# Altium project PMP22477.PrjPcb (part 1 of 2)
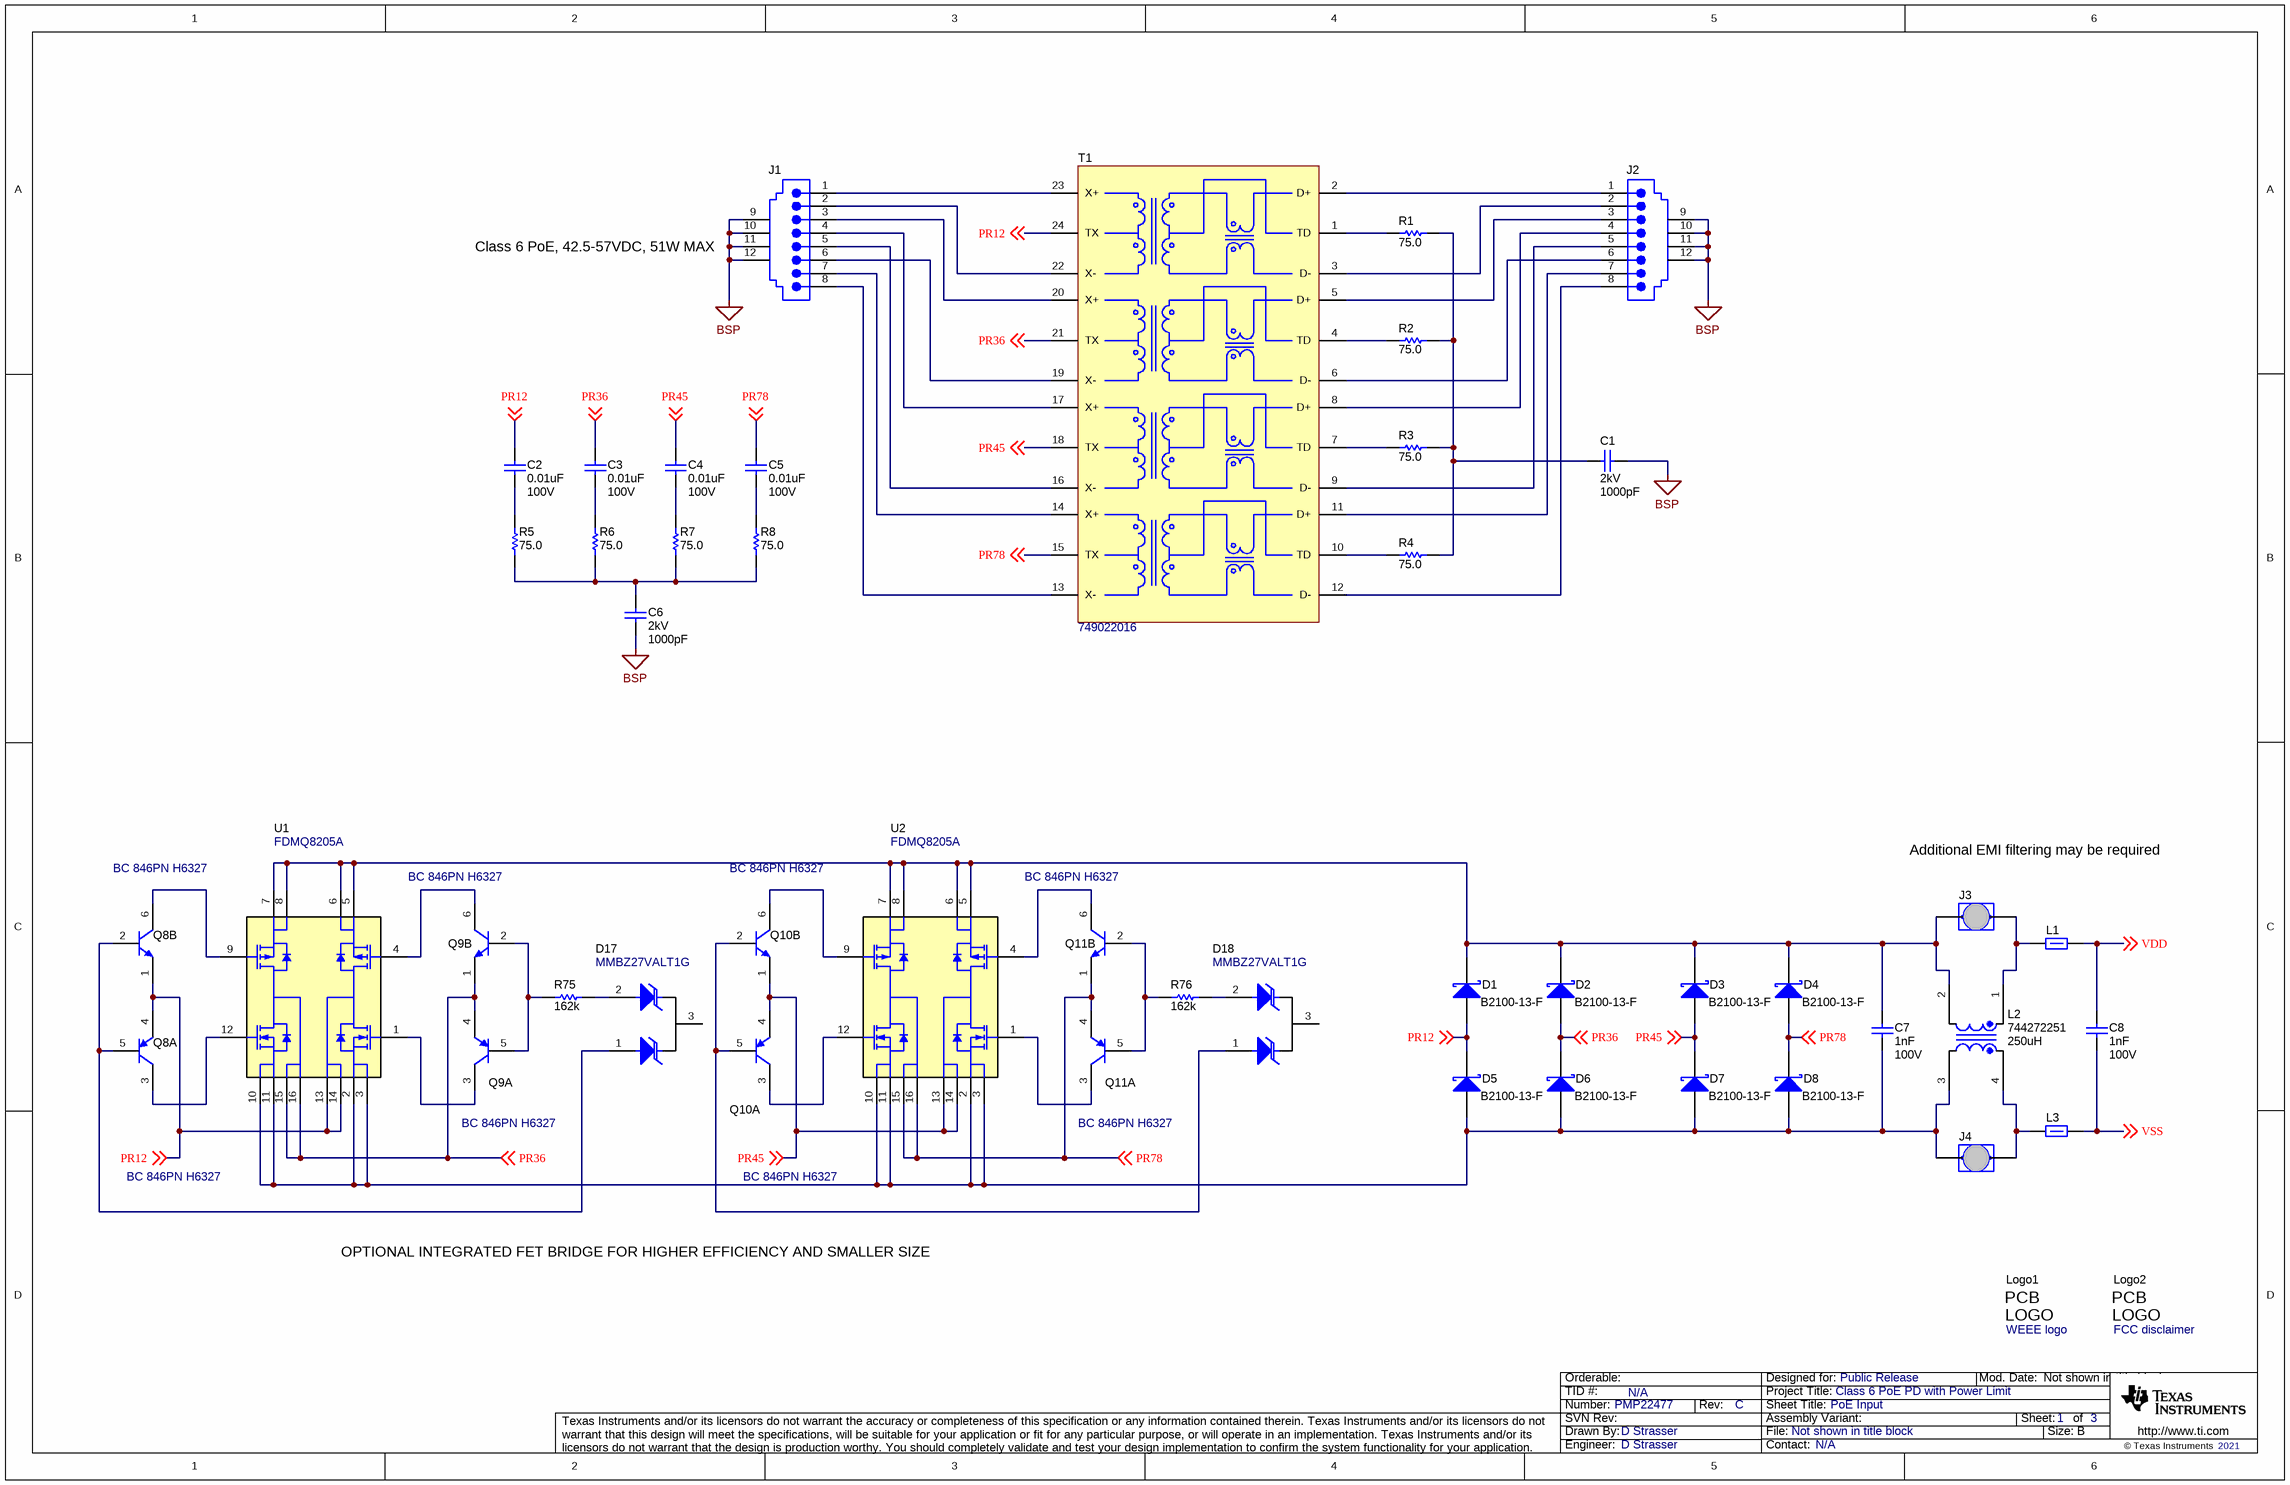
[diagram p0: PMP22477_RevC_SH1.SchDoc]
CopyrightYear: 2021; PCB_Layout: D Strasser; PCB_Rev: C; PRJ_Customer: Public Release; PRJ_Engineer: D Strasser; PRJ_Number: PMP22477; PRJ_Title: Class 6 PoE PD with Power Limit; SCH_Rev: C; TechSupport: N/A; TID: N/A
3 sheets, 191 parts. Net scope: global (net labels, ports and power ports of the same name join across sheets).
Board file: PMP22477_RevC.PcbDoc
Sheets:
  PMP22477_RevC_SH1.SchDoc
  PMP22477_RevC_SH2.SchDoc
  PMP22477_RevC_SH3.SchDoc

## Sheet PMP22477_RevC_SH1.SchDoc: PoE Input
size 431 x 279 mm; Date: Not shown in title block; ApprovedBy: Not shown in title block; CheckedBy: Not shown in title block; Author: Not shown in title block; CompanyName: Not shown in title block; DrawnBy: D Strasser; Engineer: Not shown in title block; Organization: Not shown in title block; Address1: Not shown in title block; Address2: Not shown in title block; Address3: Not shown in title block; Address4: Not shown in title block; DocumentNumber: 1; Revision: Use project parameter SCH_Rev; SheetNumber: 1; SheetTotal: 3; PageSetup: Record=PageOptions¦CenterHorizontal=True¦CenterVertical=True¦PrintScale=1.00¦XCorrection=1.00¦YCorrection=1.00¦PrintKind=0¦BorderSize=5000000¦LeftOffset=0¦BottomOffset=0¦Orientation=2¦PaperLength=1000¦PaperWidth=1000¦Scale=100¦PaperSource=15¦PrintQuality=600¦MediaType=1¦DitherType=10¦PaperKind=Letter¦PrintScaleMode=1

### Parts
C1  VDC_V: 2kV  ValueDisplayed: 1000pF  [1812]  (hidden comment: GR443QR73D102KW01L)
C2  ValueDisplayed: 0.01uF  Value2: 100V  [0603L]  (hidden comment: Capacitor)
C3  ValueDisplayed: 0.01uF  Value2: 100V  [0603L]  (hidden comment: Capacitor)
C4  ValueDisplayed: 0.01uF  Value2: 100V  [0603L]  (hidden comment: Capacitor)
C5  ValueDisplayed: 0.01uF  Value2: 100V  [0603L]  (hidden comment: Capacitor)
C6  VDC_V: 2kV  ValueDisplayed: 1000pF  [1812]  (hidden comment: GR443QR73D102KW01L)
C7  Cap_F: 1nF  VDC_V: 100V  [0603]  (hidden comment: C1608X7R2A102K080AA)
C8  Cap_F: 1nF  VDC_V: 100V  [0603]  (hidden comment: C1608X7R2A102K080AA)
D1  PartNumber: B2100-13-F  [SMB]  (hidden comment: CMP-0028397-2)
D2  PartNumber: B2100-13-F  [SMB]  (hidden comment: CMP-0028397-2)
D3  PartNumber: B2100-13-F  [SMB]  (hidden comment: CMP-0028397-2)
D4  PartNumber: B2100-13-F  [SMB]  (hidden comment: CMP-0028397-2)
D5  PartNumber: B2100-13-F  [SMB]  (hidden comment: CMP-0028397-2)
D6  PartNumber: B2100-13-F  [SMB]  (hidden comment: CMP-0028397-2)
D7  PartNumber: B2100-13-F  [SMB]  (hidden comment: CMP-0028397-2)
D8  PartNumber: B2100-13-F  [SMB]  (hidden comment: CMP-0028397-2)
D17  MMBZ27VALT1G  [SOT-23L]
D18  MMBZ27VALT1G  [SOT-23L]
J1  1-406541-1  [TEC_1-406541-1]  (value not drawn)
J2  1-406541-1  [TEC_1-406541-1]  (value not drawn)
J3  999-11-110-10-000000  [Mill-Max_999-11-110-10-000000]  (value not drawn)
J4  999-11-110-10-000000  [Mill-Max_999-11-110-10-000000]  (value not drawn)
L1  CMP-0003192-2  [0603]  (value not drawn)
L2  ValueDisplayed: 250uH  [WE-SL5]  (hidden comment: 744272251)
L3  CMP-0003192-2  [0603]  (value not drawn)
Logo1  WEEE logo  [WEEE_Minimum]  (no BOM)
Logo2  FCC disclaimer  [FCC_disclaimer]  (no BOM)
Q8  BC 846PN H6327  [SOT-363]  (parts A,B of 2)
Q9  BC 846PN H6327  [SOT-363]  (parts A,B of 2)
Q10  BC 846PN H6327  [SOT-363]  (parts A,B of 2)
Q11  BC 846PN H6327  [SOT-363]  (parts A,B of 2)
R1  ValueDisplayed: 75.0  [0603L]  (hidden comment: Resistor)
R2  ValueDisplayed: 75.0  [0603L]  (hidden comment: Resistor)
R3  ValueDisplayed: 75.0  [0603L]  (hidden comment: Resistor)
R4  ValueDisplayed: 75.0  [0603L]  (hidden comment: Resistor)
R5  ValueDisplayed: 75.0  [0603L]  (hidden comment: Resistor)
R6  ValueDisplayed: 75.0  [0603L]  (hidden comment: Resistor)
R7  ValueDisplayed: 75.0  [0603L]  (hidden comment: Resistor)
R8  ValueDisplayed: 75.0  [0603L]  (hidden comment: Resistor)
R75  ValueDisplayed: 162k  [0603L]  (hidden comment: CRCW0603162KFKEA)
R76  ValueDisplayed: 162k  [0603L]  (hidden comment: CRCW0603162KFKEA)
T1  749022016  [XFMR_749022016]
U1  FDMQ8205A  [MLP-4_5x5]
U2  FDMQ8205A  [MLP-4_5x5]

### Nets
BSP: C1.1 C6.2 J1.9 J1.10 J1.11 J1.12 J2.9 J2.10 J2.11 J2.12
PR12: C2.1 D1.2(A) D5.1(K) Q8.1(E) Q8.4(E) T1.24(TX) U1.13(INPUT1) U1.14(INPUT1) ; off-sheet PR12
PR36: C3.1 D2.2(A) D6.1(K) Q9.1(E) Q9.4(E) T1.21(TX) U1.15(INPUT2) U1.16(INPUT2) ; off-sheet PR36
PR45: C4.1 D3.2(A) D7.1(K) Q10.1(E) Q10.4(E) T1.18(TX) U2.13(INPUT1) U2.14(INPUT1) ; off-sheet PR45
PR78: C5.1 D4.2(A) D8.1(K) Q11.1(E) Q11.4(E) T1.15(TX) U2.15(INPUT2) U2.16(INPUT2) ; off-sheet PR78
VDD: C8.1 L1.2 ; off-sheet VDD
VSS: C8.2 L3.2 ; off-sheet VSS
NetC1_2: C1.2 R1.2 R2.2 R3.2 R4.1
NetC2_2: C2.2 R5.2
NetC3_2: C3.2 R6.2
NetC4_2: C4.2 R7.2
NetC5_2: C5.2 R8.2
NetC6_1: C6.1 R5.1 R6.1 R7.1 R8.1
NetC7_1: C7.1 D1.1(K) D2.1(K) D3.1(K) D4.1(K) J3.1 L2.2 U1.5(OUTP) U1.6(OUTP) U1.7(OUTP) U1.8(OUTP) U2.5(OUTP) U2.6(OUTP) U2.7(OUTP) U2.8(OUTP)
NetC7_2: C7.2 D5.2(A) D6.2(A) D7.2(A) D8.2(A) J4.1 L2.3 U1.2(OUTN) U1.3(OUTN) U1.10(OUTN) U1.11(OUTN) U2.2(OUTN) U2.3(OUTN) U2.10(OUTN) U2.11(OUTN)
NetD17_1: D17.1 Q8.2(B) Q8.5(B)
NetD17_2: D17.2 R75.2
NetD18_1: D18.1 Q10.2(B) Q10.5(B)
NetD18_2: D18.2 R76.2
NetJ1_1: J1.1 T1.23(X+)
NetJ1_2: J1.2 T1.22(X-)
NetJ1_3: J1.3 T1.20(X+)
NetJ1_4: J1.4 T1.17(X+)
NetJ1_5: J1.5 T1.16(X-)
NetJ1_6: J1.6 T1.19(X-)
NetJ1_7: J1.7 T1.14(X+)
NetJ1_8: J1.8 T1.13(X-)
NetJ2_1: J2.1 T1.2(D+)
NetJ2_2: J2.2 T1.3(D-)
NetJ2_3: J2.3 T1.5(D+)
NetJ2_4: J2.4 T1.8(D+)
NetJ2_5: J2.5 T1.9(D-)
NetJ2_6: J2.6 T1.6(D-)
NetJ2_7: J2.7 T1.11(D+)
NetJ2_8: J2.8 T1.12(D-)
NetJ3_2: J3.2 L1.1 L2.1
NetJ4_2: J4.2 L2.4 L3.1
NetQ8_3: Q8.3(C) U1.12(G4)
NetQ8_6: Q8.6(C) U1.9(G3)
NetQ9_2: Q9.2(B) Q9.5(B) R75.1
NetQ9_3: Q9.3(C) U1.1(G1)
NetQ9_6: Q9.6(C) U1.4(G2)
NetQ10_3: Q10.3(C) U2.12(G4)
NetQ10_6: Q10.6(C) U2.9(G3)
NetQ11_2: Q11.2(B) Q11.5(B) R76.1
NetQ11_3: Q11.3(C) U2.1(G1)
NetQ11_6: Q11.6(C) U2.4(G2)
NetR1_1: R1.1 T1.1(TD)
NetR2_1: R2.1 T1.4(TD)
NetR3_1: R3.1 T1.7(TD)
NetR4_2: R4.2 T1.10(TD)

Not connected (* = marked no-connect by the designer): D17 3; D18 3

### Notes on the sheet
- Class 6 PoE, 42.5-57VDC, 51W MAX
- Additional EMI filtering may be required
- OPTIONAL INTEGRATED FET BRIDGE FOR HIGHER EFFICIENCY AND SMALLER SIZE

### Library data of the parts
C1 C6 = CMP-0009438-2: CAP, CERM, 1000 pF, 2000 V, +/- 10%, X7R, 1812; Manufacturer: MuRata; TaMin_C: -55°C; Polarized: N; SizeAreaWB_mm2: 23.1; Value1: Unknown; U/M: EA; Value: 1000pF; TaMax_C: 125°C; SizeZ_mm: 1.35; SizeX_mm: 4.5; SizeY_mm: 3.2; Value2: 2000V; SizeArea_mm2: 14.4; Cap_F: 1nF; AEC Category: Q200
C2-C5 = CMP-0007468-5: CAP, CERM, 0.01 uF, 100 V, +/- 10%, X7R, 0603; PartNumber: GRM188R72A103KA01D; Manufacturer: MuRata; Polarized: N; Value: 0.01uF; U/M: EA; Cap_F: 10nF; Value1: Unknown; TaMin_C: -55°C; TaMax_C: 125°C; Cap_Case: 0603; SizeArea_mm2: 1.28; SizeAreaWB_mm2: 4.68; SizeX_mm: 1.6; SizeY_mm: 0.8; SizeZ_mm: 1; AEC Category: Q200
C7 C8 = CMP-0007053-4: CAP, CERM, 1000 pF, 100 V, +/- 10%, X7R, 0603; Manufacturer: TDK; Polarized: N; Value: 1000pF; U/M: EA; Value1: Unknown; TaMin_C: -55°C; TaMax_C: 125°C; SizeAreaWB_mm2: 4.68; SizeZ_mm: 1; SizeX_mm: 1.6; SizeY_mm: 0.8; SizeArea_mm2: 1.28; AEC Category: Q200
D1-D8 = CMP-0028397-2: Diode, Schottky, 100 V, 2 A, SMB; Manufacturer: Diodes Inc.; Vf_V: 790mV; Value: 100V; Value1: 2A; Value2: 0.79V; TJmax_C: 150°C; RJC_CperW: 15; SizeArea_mm2: 21.336; Green_REACh: Passed; Green_Lifecycle: Active; SizeY_mm: 3.81; AEC Category: Q101; SizeZ_mm: 2.6; SizeAreaWB_mm2: 44.156; SizeX_mm: 5.6
D17 D18 = CMP-0005922-4: Diode, TVS, Uni, 27 V, SOT-23; Manufacturer: ON Semiconductor; SizeAreaWB_mm2: 14; SizeX_mm: 2.5; SizeArea_mm2: 7.5; Value: 27V; RJA_CperW: 556; Ppk: 40W; SizeY_mm: 3; AEC Category: Q101; SizeZ_mm: 1.1
J1 J2 = CMP-0054918-1: RJ45, No LED, tab up, R/A, TH; Manufacturer: TE Connectivity; CNHeader: FALSE; Green_Lifecycle: Active; Green_REACh: Passed; ContactFinish: Gold; CT: TRUE
J3 J4 = CMP-0055047-1: Shorting Jumper, 2.54mm, 2 Position, Gold, TH; Manufacturer: Mill-Max; CNHeader: FALSE; Gender: Male; Pitch_mm: 2.54; Cert_UL: Y
L1 L3 = CMP-0003192-2: Ferrite Bead, 300 ohm @ 100 MHz, 2 A, 0603; PartNumber: 742792641; Manufacturer: Wurth Elektronik; Value: 300 ohm; Imax_A: 2A; DCR_ohm: 0.15; Value1: 0.15 ohm; ZTyp@100MHz_Ohm: 300; Ztyp@1GHz_Ohm: 273.989; SizeAreaWB_mm2: 4.68; SizeZ_mm: 1; SizeX_mm: 1.6; SizeY_mm: 0.8; SizeArea_mm2: 1.28
L2 = CMP-0013220-2: Coupled inductor, 250 uH,  A, 0.035 ohm, SMD; Manufacturer: Wurth Elektronik; DCR_ohm: 0.035; Value: 250uH; Ind_H: 250µH
Logo1 = CMP-0074769-1
Logo2 = CMP-0074847-1: FCC_disclaimer
Q8-Q11 = CMP-0000518-2: Transistor, NPN/PNP Pair, 65 V, 0.1 A, SOT-363; Manufacturer: Infineon Technologies; TaMax_C: 150°C; Value2: 450; Value1: 0.1 A; Vcesat1_V: 200mV; SizeX_mm: 2.2; TaMin_C: -65°C; IcRated_A: 100mA; CompType: BJT; SizeZ_mm: 1.1; AEC Qualified: N; Value: 65 V; SizeArea_mm2: 4.84; NPN: 1; Vceo_V: 65V; AEC Category: Q101; SizeAreaWB_mm2: 10.24; U/M: EA
R1-R8 = CMP-0022590-4: RES, 75.0, 1%, 0.1 W, AEC-Q200 Grade 0, 0603; PartNumber: CRCW060375R0FKEA; Manufacturer: Vishay-Dale; Value: 75.0; Res_ohm: 75; Value_Code: 75R0; Power_W: 100mW; Value2: 0.1W; VDC_V: 75V; TempCo: 100 ppm/C; SizeArea_mm2: 1.28; SizeX_mm: 1.6; SizeY_mm: 0.8; SizeZ_mm: 1; EIA_Code: E96; AEC Category: Q200; AEC Qualified: Y; AEC Grade: 0
R75 R76 = CMP-0022073-4: RES, 162 k, 1%, 0.1 W, AEC-Q200 Grade 0, 0603; Manufacturer: Vishay-Dale; Power_W: 100mW; TempCo: 100 ppm/C; Value: 162k; EIA_Code: E96; SizeX_mm: 1.6; SizeY_mm: 0.8; SizeZ_mm: 1; Value2: 0.1W; SizeArea_mm2: 1.28; AEC Qualified: Y; VDC_V: 75V; AEC Category: Q200; AEC Grade: 0
T1 = CMP-0030730-1: Transformer, PoE+, SMT; Manufacturer: Wurth Elektronik; Value: 350uH; Ind_H: 350µH; Lp: 350
U1 U2 = CMP-0005142-3: GreenBridge 2 Series of High-Efficiency Bridge Rectifiers; Manufacturer: Fairchild Semiconductor; SizeZ_mm: 0.8; SizeX_mm: 4.5; SizeY_mm: 5; SizeArea_mm2: 22.5; SizeAreaWB_mm2: 45.5

## Sheet PMP22477_RevC_SH2.SchDoc: Power Limit Circuit
size 431 x 279 mm; Date: Not shown in title block; ApprovedBy: Not shown in title block; CheckedBy: Not shown in title block; Author: Not shown in title block; CompanyName: Not shown in title block; DrawnBy: D Strasser; Engineer: Not shown in title block; Organization: Not shown in title block; Address1: Not shown in title block; Address2: Not shown in title block; Address3: Not shown in title block; Address4: Not shown in title block; DocumentNumber: 2; Revision: Use project parameter SCH_Rev; SheetNumber: 2; SheetTotal: 3; PageSetup: Record=PageOptions¦CenterHorizontal=True¦CenterVertical=True¦PrintScale=1.00¦XCorrection=1.00¦YCorrection=1.00¦PrintKind=0¦BorderSize=5000000¦LeftOffset=0¦BottomOffset=0¦Orientation=2¦PaperLength=1000¦PaperWidth=1000¦Scale=100¦PaperSource=15¦PrintQuality=600¦MediaType=1¦DitherType=10¦PaperKind=Letter¦PrintScaleMode=1
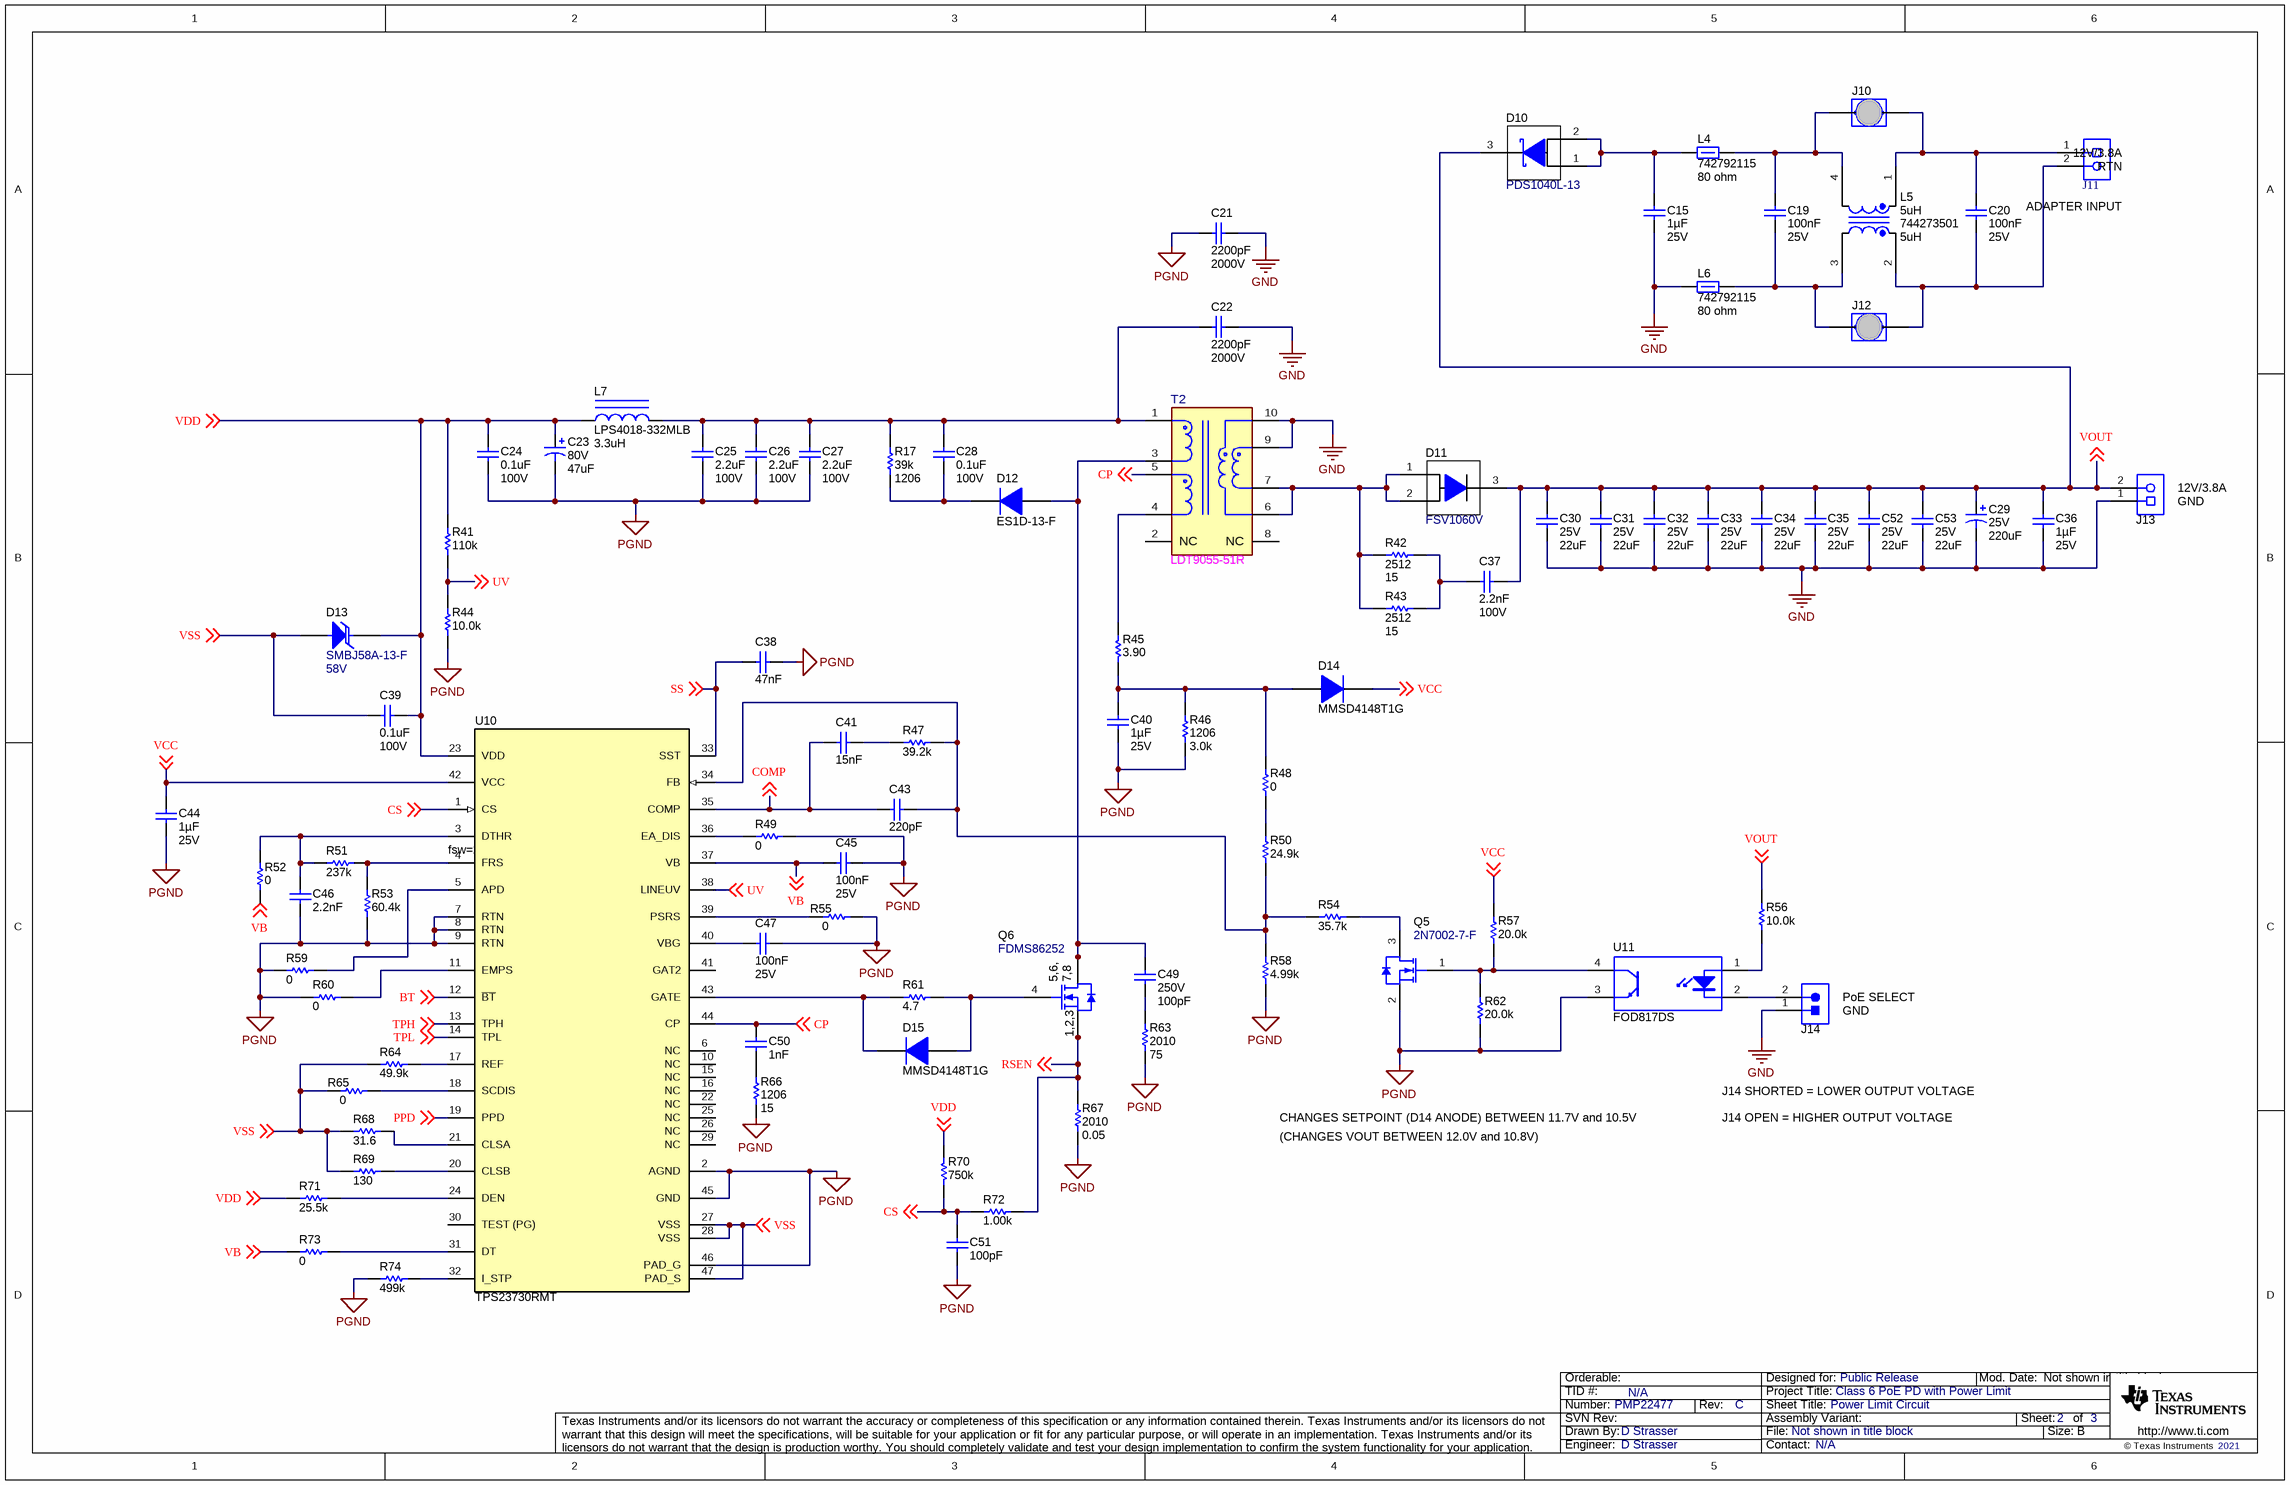
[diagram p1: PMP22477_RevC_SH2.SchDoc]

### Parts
C15  Cap_F: 1µF  VDC_V: 25V  [0603L]  (hidden comment: GRJ188R71E105KE11D)
C19  Cap_F: 100nF  VDC_V: 25V  [0603L]  (hidden comment: C0603C104J3RACTU)
C20  Cap_F: 100nF  VDC_V: 25V  [0603L]  (hidden comment: C0603C104J3RACTU)
C21  ValueDisplayed: 2200pF  Value2: 2000V  [1812_HV]  (hidden comment: Capacitor)
C22  ValueDisplayed: 2200pF  Value2: 2000V  [1812_HV]  (hidden comment: Capacitor)
C23  VDC_V: 80V  ValueDisplayed: 47uF  [SM_RADIAL_G]  (hidden comment: EEE-FK1K470P)
C24  ValueDisplayed: 0.1uF  Value2: 100V  [0805_HV]  (hidden comment: Capacitor)
C25  ValueDisplayed: 2.2uF  Value2: 100V  [1210_270]  (hidden comment: Capacitor)
C26  ValueDisplayed: 2.2uF  Value2: 100V  [1210_270]  (hidden comment: Capacitor)
C27  ValueDisplayed: 2.2uF  Value2: 100V  [1210_270]  (hidden comment: Capacitor)
C28  ValueDisplayed: 0.1uF  Value2: 100V  [0805_HV]  (hidden comment: Capacitor)
C29  VDC_V: 25V  ValueDisplayed: 220uF  [SM_RADIAL_F]  (hidden comment: EEE-FK1E221P)
C30  VDC_V: 25V  ValueDisplayed: 22uF  [1210_270]  (hidden comment: GRM32ER71E226KE15L)
C31  VDC_V: 25V  ValueDisplayed: 22uF  [1210_270]  (hidden comment: GRM32ER71E226KE15L)
C32  VDC_V: 25V  ValueDisplayed: 22uF  [1210_270]  (hidden comment: GRM32ER71E226KE15L)
C33  VDC_V: 25V  ValueDisplayed: 22uF  [1210_270]  (hidden comment: GRM32ER71E226KE15L)
C34  VDC_V: 25V  ValueDisplayed: 22uF  [1210_270]  (hidden comment: GRM32ER71E226KE15L)
C35  VDC_V: 25V  ValueDisplayed: 22uF  [1210_270]  (hidden comment: GRM32ER71E226KE15L)
C36  Cap_F: 1µF  VDC_V: 25V  [0603L]  (hidden comment: GRJ188R71E105KE11D)
C37  Cap_F: 2.2nF  VDC_V: 100V  [0603]  (hidden comment: 06031C222KAT2A)
C38  Cap_F: 47nF  [0603L]  (hidden comment: GRM188R71C473KA01D)
C39  ValueDisplayed: 0.1uF  Value2: 100V  [0805_HV]  (hidden comment: Capacitor)
C40  Cap_F: 1µF  VDC_V: 25V  [0603L]  (hidden comment: GRJ188R71E105KE11D)
C41  Cap_F: 15nF  [0603L]  (hidden comment: C1608X7R1H153K080AA)
C43  Cap_F: 220pF  [0603L]  (hidden comment: GRM188R71H221KA01D)
C44  Cap_F: 1µF  VDC_V: 25V  [0603L]  (hidden comment: GRJ188R71E105KE11D)
C45  Cap_F: 100nF  VDC_V: 25V  [0603L]  (hidden comment: C0603C104J3RACTU)
C46  Cap_F: 2.2nF  [0603L]  (hidden comment: C0603C222K5RAC)
C47  Cap_F: 100nF  VDC_V: 25V  [0603L]  (hidden comment: C0603C104J3RACTU)
C49  VDC_V: 250V  ValueDisplayed: 100pF  [0805_HV]  (hidden comment: GRM21A5C2E101JW01D)
C50  Cap_F: 1nF  [0603L]  (hidden comment: 885012206083)
C51  ValueDisplayed: 100pF  [0603]  (hidden comment: 885012006057)
C52  VDC_V: 25V  ValueDisplayed: 22uF  [1210_270]  (hidden comment: GRM32ER71E226KE15L)
C53  VDC_V: 25V  ValueDisplayed: 22uF  [1210_270]  (hidden comment: GRM32ER71E226KE15L)
D10  PDS1040L-13  [POWERDI5]
D11  FSV1060V  [TO-277A]
D12  ES1D-13-F  [SMA]
D13  SMBJ58A-13-F  value 58V  [SMB]
D14  MMSD4148T1G  [SOD-123]
D15  MMSD4148T1G  [SOD-123]
J10  999-11-110-10-000000  [Mill-Max_999-11-110-10-000000]  (value not drawn)
J11  CMP-0074913-1  [TERM_BLK_ED555-2DS]  (value not drawn)
J12  999-11-110-10-000000  [Mill-Max_999-11-110-10-000000]  (value not drawn)
J13  Receptacle_2x1  [TERM_BLK_ED555-2DS]  (value not drawn)
J14  TSW-102-07-G-S  [TSW-102-07-G-S]  (value not drawn)
L4  742792115  ValueDisplayed: 80 ohm  [1206]
L5  value 5uH  [WE-SL5_HC]  (hidden comment: 744273501)
L6  742792115  ValueDisplayed: 80 ohm  [1206]
L7  ValueDisplayed: 3.3uH  [LPS4018]  (hidden comment: LPS4018-332MLB)
Q5  2N7002-7-F  [SOT-23L]
Q6  FDMS86252  [TRANS_Fairchild_PQFN08A]
R17  ValueDisplayed: 39k  PackageReference: 1206  [1206L]  (hidden comment: Resistor)
R41  ValueDisplayed: 110k  [0603L]  (hidden comment: CRCW0603110KFKEA)
R42  ValueDisplayed: 15  [2512]  (hidden comment: CRCW251215R0JNEG)
R43  ValueDisplayed: 15  [2512]  (hidden comment: CRCW251215R0JNEG)
R44  ValueDisplayed: 10.0k  [0603L]  (hidden comment: CRCW060310K0FKEA)
R45  ValueDisplayed: 3.90  [0805_HV]  (hidden comment: ERJ-6RQF3R9V)
R46  ValueDisplayed: 3.0k  [1206]  (hidden comment: CRCW12063K00JNEA)
R47  ValueDisplayed: 39.2k  [0603L]  (hidden comment: CRCW060339K2FKEA)
R48  ValueDisplayed: 0  [0603L]  (hidden comment: ERJ-3GEY0R00V)
R49  ValueDisplayed: 0  [0603L]  (hidden comment: ERJ-3GEY0R00V)
R50  ValueDisplayed: 24.9k  [0603L]  (hidden comment: RC0603FR-0724K9L)
R51  ValueDisplayed: 237k  [0603L]  (hidden comment: RC0603FR-07237KL)
R52  ValueDisplayed: 0  [0603L]  (hidden comment: ERJ-3GEY0R00V)
R53  ValueDisplayed: 60.4k  [0603L]  (hidden comment: CRCW060360K4FKEA)
R54  ValueDisplayed: 35.7k  [0603L]  (hidden comment: RC0603FR-0735K7L)
R55  ValueDisplayed: 0  [0603L]  (hidden comment: ERJ-3GEY0R00V)
R56  ValueDisplayed: 10.0k  [0603L]  (hidden comment: CRCW060310K0FKEA)
R57  ValueDisplayed: 20.0k  [0603L]  (hidden comment: CRCW060320K0FKEA)
R58  ValueDisplayed: 4.99k  [0603L]  (hidden comment: CRCW06034K99FKEA)
R59  ValueDisplayed: 0  [0603L]  (hidden comment: ERJ-3GEY0R00V)
R60  ValueDisplayed: 0  [0603L]  (hidden comment: ERJ-3GEY0R00V)
R61  ValueDisplayed: 4.7  [0603L]  (hidden comment: CRCW06034R70JNEA)
R62  ValueDisplayed: 20.0k  [0603L]  (hidden comment: CRCW060320K0FKEA)
R63  ValueDisplayed: 75  [2010]  (hidden comment: CRCW201075R0JNEF)
R64  ValueDisplayed: 49.9k  [0603L]  (hidden comment: CRCW060349K9FKEA)
R65  ValueDisplayed: 0  [0603L]  (hidden comment: ERJ-3GEY0R00V)
R66  PackageReference: 1206  ValueDisplayed: 15  [1206L]  (hidden comment: CRCW120615R0JNEA)
R67  ValueDisplayed: 0.05  [2010]  (hidden comment: CSRN2010FK50L0)
R68  ValueDisplayed: 31.6  [0805_HV]  (hidden comment: CRCW080531R6FKEA)
R69  ValueDisplayed: 130  [0805_HV]  (hidden comment: CRCW0805130RFKEA)
R70  ValueDisplayed: 750k  [0603L]  (hidden comment: CRCW0603750KJNEA)
R71  ValueDisplayed: 25.5k  [0603L]  (hidden comment: RC0603FR-0725K5L)
R72  ValueDisplayed: 1.00k  [0603L]  (hidden comment: CRCW06031K00FKEA)
R73  ValueDisplayed: 0  [0603L]  (hidden comment: ERJ-3GEY0R00V)
R74  ValueDisplayed: 499k  [0603L]  (hidden comment: CRCW0603499KFKEA)
T2  LDT9055-51R  [FP-LDT9055-B_SMT_27MM5_26MM0-MFG]
U10  TPS23730RMT  [RMT0045A]
U11  FOD817DS  [N04C]

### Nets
GND: C15.2 C21.1 C22.1 C29.2(-) C30.1 C31.1 C32.1 C33.1 C34.1 C35.1 C36.2 C52.1 C53.1 J13.1 J14.1 L6.1 T2.9 T2.10
PGND: C21.2 C23.2(-) C24.2 C25.2 C26.2 C27.2 C38.2 C40.2 C44.2 C45.2 C46.2 C47.1 C51.1 Q5.2(S) R44.1 R46.1 R49.2 R53.1 R55.2 R58.2 R59.1 R60.1 R62.2 R63.2 R66.2 R67.2 R74.1 U10.2(AGND) U10.7(RTN) U10.8(RTN) U10.9(RTN) U10.45(GND) U10.46(PAD_G) U11.3(E)
BT: U10.12(~{BT}) ; off-sheet BT
COMP: C41.2 C43.2 U10.35(COMP) ; off-sheet COMP
CP: C50.1 T2.5 U10.44(CP) ; off-sheet CP
CS: C51.2 R70.1 R72.1 U10.1(CS) ; off-sheet CS
PPD: U10.19(PPD) ; off-sheet PPD
RSEN: Q6.1(S) Q6.2(S) Q6.3(S) R67.1 R72.2 ; off-sheet RSEN
SS: C38.1 U10.33(SST) ; off-sheet SS
TPH: U10.13(TPH) ; off-sheet TPH
TPL: U10.14(TPL) ; off-sheet TPL
UV: R41.1 R44.2 U10.38(LINEUV) ; off-sheet UV
VB: C45.1 R52.1 R73.1 U10.37(VB) ; off-sheet VB
VCC: C44.1 D14.1(K) R57.1 U10.42(VCC) ; off-sheet VCC
VDD: C23.1(+) C24.1 C39.1 D13.1(K) L7.1 R41.2 R70.2 R71.1 U10.23(VDD) ; off-sheet VDD
VOUT: C29.1(+) C30.2 C31.2 C32.2 C33.2 C34.2 C35.2 C36.1 C37.1 C52.2 C53.2 D10.3(K) D11.3(K) J13.2 R56.1 ; off-sheet VOUT
VSS: C39.2 D13.2(A) R64.1 R65.1 R68.1 R69.1 U10.27(VSS) U10.28(VSS) U10.47(PAD_S) ; off-sheet VSS
NetC15_1: C15.1 D10.1(A) D10.2(A) L4.1
NetC19_1: C19.1 J12.1 L5.3 L6.2
NetC19_2: C19.2 J10.1 L4.2 L5.4
NetC20_1: C20.1 J11.2 J12.2 L5.2
NetC20_2: C20.2 J10.2 J11.1 L5.1
NetC22_2: C22.2 C25.1 C26.1 C27.1 C28.2 L7.2 R17.2 T2.1
NetC28_1: C28.1 D12.1(K) R17.1
NetC37_2: C37.2 R42.2 R43.2
NetC40_1: C40.1 D14.2(A) R45.1 R46.2 R48.2
NetC41_1: C41.1 R47.1
NetC43_1: C43.1 R47.2 R50.1 R54.1 R58.1 U10.34(FB)
NetC46_1: C46.1 R51.1 R52.2 U10.3(DTHR)
NetC47_2: C47.2 U10.40(VBG)
NetC49_1: C49.1 R63.1
NetC49_2: C49.2 D12.2(A) Q6.5(D) Q6.6(D) Q6.7(D) Q6.8(D) T2.3
NetC50_2: C50.2 R66.1
NetD11_1: D11.1(A) D11.2(A) R42.1 R43.1 T2.6 T2.7
NetD15_1: D15.1(K) R61.1 U10.43(GATE)
NetD15_2: D15.2(A) Q6.4(G) R61.2
NetJ14_2: J14.2 U11.2(K)
NetQ5_1: Q5.1(G) R57.2 R62.1 U11.4(C)
NetQ5_3: Q5.3(D) R54.2
NetR45_2: R45.2 T2.4
NetR48_1: R48.1 R50.2
NetR49_1: R49.1 U10.36(EA_DIS)
NetR51_2: R51.2 R53.2 U10.4(FRS)
NetR55_1: R55.1 U10.39(PSRS)
NetR56_2: R56.2 U11.1(A)
NetR59_2: R59.2 U10.5(APD)
NetR60_2: R60.2 U10.11(EMPS)
NetR64_2: R64.2 U10.17(REF)
NetR65_2: R65.2 U10.18(SCDIS)
NetR68_2: R68.2 U10.21(CLSA)
NetR69_2: R69.2 U10.20(CLSB)
NetR71_2: R71.2 U10.24(DEN)
NetR73_2: R73.2 U10.31(DT)
NetR74_2: R74.2 U10.32(I_STP)

Not connected (* = marked no-connect by the designer): T2 2(NC) 8(NC); U10 6(NC) 10(NC) 15(NC) 16(NC) 22(NC) 25(NC) 26(NC) 29(NC) 30(TEST_(PG)) 41(GAT2)

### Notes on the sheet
- (near J11) 12V/3.8A
- (near J11) RTN
- (near J11) ADAPTER INPUT
- (near J13) GND
- (near J13) 12V/3.8A
- fsw=250KHz
- (near J14) PoE SELECT
- (near J14) GND
- J14 SHORTED = LOWER OUTPUT VOLTAGE
- CHANGES SETPOINT (D14 ANODE) BETWEEN 11.7V and 10.5V
- (CHANGES VOUT BETWEEN 12.0V and 10.8V)
- J14 OPEN = HIGHER OUTPUT VOLTAGE

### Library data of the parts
C15 C36 C40 C44 = CMP-0079720-1: CAP, CERM, 1 µF, 25 V,+/- 10%, X7R, 0603; Manufacturer: MuRata; TaMin_C: -55°C; Polarized: N; SizeAreaWB_mm2: 4.68; U/M: EA; Value: 1uF; TaMax_C: 125°C; SizeZ_mm: 1; SizeX_mm: 1.6; SizeY_mm: 0.8; Cap_Case: 0603; SizeArea_mm2: 1.28; AEC Category: Q200
C19 C20 C45 C47 = CMP-0006856-6: CAP, CERM, 0.1 uF, 25 V, +/- 5%, X7R, 0603; Manufacturer: Kemet; TaMin_C: -55°C; Polarized: N; SizeAreaWB_mm2: 4.68; Value1: Unknown; U/M: EA; Value: 0.1uF; TaMax_C: 125°C; SizeZ_mm: 1; SizeX_mm: 1.6; SizeY_mm: 0.8; Cap_Case: 0603; SizeArea_mm2: 1.28; AEC Category: Q200
C21 C22 = CMP-0009358-2: CAP, CERM, 2200 pF, 2000 V, +/- 10%, X7R, 1812; PartNumber: C4532X7R3D222K130KA; Manufacturer: TDK; Polarized: N; Value: 2200pF; U/M: EA; Cap_F: 2.2nF; Value1: Unknown; VDC_V: 2kV; TaMin_C: -55°C; TaMax_C: 125°C; Cap_Case: 1812; SizeArea_mm2: 14.4; SizeAreaWB_mm2: 23.1; SizeX_mm: 4.5; SizeY_mm: 3.2; SizeZ_mm: 1.35; AEC Category: Q200
C23 = CMP-0011200-2: CAP, AL, 47 uF, 80 V, +/- 20%, 0.7 ohm, AEC-Q200 Grade 2, SMD; Manufacturer: Panasonic; TaMin_C: -55°C; ESR_ohm: 0.7; Polarized: Y; SizeAreaWB_mm2: 172.2; Value1: 0.7 ohm; U/M: EA; Value: 47uF; TaMax_C: 105°C; SizeZ_mm: 10.2; SizeX_mm: 12; SizeY_mm: 10.3; Cap_Case: G; SizeArea_mm2: 123.6; CompType: Capacitor; Cap_F: 47µF; IRMS_A: 200mA; AEC Grade: 2; AEC Category: Q200
C24 C28 C39 = CMP-0007886-2: CAP, CERM, 0.1 uF, 100 V, +/- 10%, X7R, 0805; PartNumber: C2012X7R2A104K125AA; Manufacturer: TDK; Polarized: N; Value: 0.1uF; U/M: EA; Cap_F: 100nF; ESR_ohm: 0.020726; Value1: 0.020726 ohm; IRMS_A: 1.456A; TaMin_C: -55°C; TaMax_C: 125°C; Cap_Case: 0805; SizeArea_mm2: 2.5; SizeAreaWB_mm2: 6.75; SizeX_mm: 2; SizeY_mm: 1.25; SizeZ_mm: 1.45; AEC Category: Q200
C25-C27 = CMP-0009232-2: CAP, CERM, 2.2 uF, 100 V, +/- 10%, X7R, 1210; PartNumber: GRM32ER72A225KA35L; Manufacturer: MuRata; Polarized: N; Value: 2.2uF; U/M: EA; Cap_F: 2.2µF; ESR_ohm: 7m; Value1: 0.007 ohm; IRMS_A: 4.4A; TaMin_C: -55°C; TaMax_C: 125°C; Cap_Case: 1210; SizeArea_mm2: 8; SizeAreaWB_mm2: 14.7; SizeX_mm: 3.2; SizeY_mm: 2.5; SizeZ_mm: 2.7; AEC Category: Q200
C29 = CMP-0010714-1: CAP, AL, 220 uF, 25 V, +/- 20%, 0.16 ohm, AEC-Q200 Grade 2, SMD; Manufacturer: Panasonic; TaMin_C: -55°C; ESR_ohm: 0.16; Polarized: Y; SizeAreaWB_mm2: 123.6; U/M: EA; Value: 220uF; TaMax_C: 105°C; SizeZ_mm: 10.2; SizeX_mm: 10; SizeY_mm: 8.3; Cap_Case: F; SizeArea_mm2: 83; CompType: Capacitor; Cap_F: 220µF; IRMS_A: 600mA; AEC Grade: 2; AEC Category: Q200
C30-C35 C52 C53 = CMP-0009224-2: CAP, CERM, 22 uF, 25 V, +/- 10%, X7R, 1210; Manufacturer: MuRata; TaMin_C: -55°C; Polarized: N; SizeAreaWB_mm2: 14.7; Value1: Unknown; U/M: EA; Value: 22uF; TaMax_C: 125°C; SizeZ_mm: 2.7; SizeX_mm: 3.2; SizeY_mm: 2.5; Cap_Case: 1210; SizeArea_mm2: 8; Cap_F: 22µF; AEC Category: Q200
C37 = CMP-0006737-4: CAP, CERM, 2200 pF, 100 V, +/- 10%, X7R, 0603; Manufacturer: AVX; TaMin_C: -55°C; ESR_ohm: 0.192; Polarized: N; SizeAreaWB_mm2: 4.68; Value1: 0.192 ohm; U/M: EA; Value: 2200pF; TaMax_C: 125°C; SizeZ_mm: 1; SizeX_mm: 1.6; SizeY_mm: 0.8; SizeArea_mm2: 1.28; AEC Category: Q200
C38 = CMP-0007397-4: CAP, CERM, 0.047 uF, 16 V, +/- 10%, X7R, 0603; Manufacturer: MuRata; TaMin_C: -55°C; Polarized: N; SizeAreaWB_mm2: 4.68; Value1: Unknown; U/M: EA; TaMax_C: 125°C; SizeZ_mm: 1; SizeX_mm: 1.6; SizeY_mm: 0.8; Cap_Case: 0603; Value2: 16V; SizeArea_mm2: 1.28; AEC Category: Q200
C41 = CMP-0007045-5: CAP, CERM, 0.015 uF, 50 V, +/- 10%, X7R, AEC-Q200 Grade 1, 0603; Manufacturer: TDK; TaMin_C: -55°C; Polarized: N; SizeAreaWB_mm2: 4.68; Value1: Unknown; U/M: EA; TaMax_C: 125°C; SizeZ_mm: 1; SizeX_mm: 1.6; SizeY_mm: 0.8; Cap_Case: 0603; Value2: 50V; SizeArea_mm2: 1.28; AEC Qualified: Y; AEC Category: Q200
C43 = CMP-0007442-5: CAP, CERM, 220 pF, 50 V, +/- 10%, X7R, 0603; Manufacturer: MuRata; TaMin_C: -55°C; Polarized: N; SizeAreaWB_mm2: 4.68; Value1: Unknown; U/M: EA; Value: 220pF; TaMax_C: 125°C; SizeZ_mm: 1; SizeX_mm: 1.6; SizeY_mm: 0.8; Cap_Case: 0603; Value2: 50V; SizeArea_mm2: 1.28; AEC Category: Q200
C46 = CMP-0006897-4: CAP, CERM, 2200 pF, 50 V, +/- 10%, X7R, 0603; Manufacturer: Kemet; TaMin_C: -55°C; Polarized: N; SizeAreaWB_mm2: 4.68; Value1: Unknown; U/M: EA; Value: 2200pF; TaMax_C: 125°C; SizeZ_mm: 1; SizeX_mm: 1.6; SizeY_mm: 0.8; Cap_Case: 0603; Value2: 50V; SizeArea_mm2: 1.28; AEC Category: Q200
C49 = CMP-0008236-2: CAP, CERM, 100 pF, 250 V, +/- 5%, C0G/NP0, 0805; Manufacturer: MuRata; TaMin_C: -55°C; Polarized: N; SizeAreaWB_mm2: 6.75; Value1: Unknown; U/M: EA; Value: 100pF; TaMax_C: 125°C; SizeZ_mm: 1.45; SizeX_mm: 2; SizeY_mm: 1.25; Cap_Case: 0805; SizeArea_mm2: 2.5; AEC Category: Q200
C50 = CMP-0064933-4: CAP, CERM, 1000 pF, 50 V,+/- 10%, X7R, 0603; Manufacturer: Wurth Elektronik; TaMin_C: -55°C; Polarized: N; SizeAreaWB_mm2: 4.68; Value1: Unknown; U/M: EA; Value: 1000pF; TaMax_C: 125°C; SizeZ_mm: 1; SizeX_mm: 1.6; SizeY_mm: 0.8; Cap_Case: 0603; Value2: 50V; SizeArea_mm2: 1.28; AEC Category: Q200
C51 = CMP-0006822-4: CAP, CERM, 100 pF, 50 V, +/- 5%, C0G/NP0, 0603; Manufacturer: Wurth Elektronik; TaMin_C: -55°C; Polarized: N; SizeAreaWB_mm2: 4.68; Value1: Unknown; U/M: EA; Value: 100pF; TaMax_C: 125°C; SizeZ_mm: 1; SizeX_mm: 1.6; SizeY_mm: 0.8; Value2: 50V; SizeArea_mm2: 1.28; AEC Category: Q200
D10 = CMP-0028634-2: Diode, Schottky, 40 V, 10 A, PowerDI5; Manufacturer: Diodes Inc.; Value2: 0.49V; Vf_V: 490mV; AEC Category: Q101; Value: 40V; Value1: 10A; RJC_CperW: 85; Green_Lifecycle: Active; SizeY_mm: 3.9; SizeArea_mm2: 24.96; Green_REACh: Passed; SizeX_mm: 6.4; TJmax_C: 150°C; SizeZ_mm: 1.05; SizeAreaWB_mm2: 49.56
D11 = CMP-0028980-2: Diode, Schottky, 60 V, 10 A, TO-277A; Manufacturer: Fairchild Semiconductor; SizeX_mm: 6.5; Vf_V: 520mV; SizeAreaWB_mm2: 57.375; AEC Category: Q101; AEC Qualified: N; Vr_V: 60V; Value: 60V; RJC_CperW: 13; Io_A: 10A; TJmax_C: 150°C; SizeArea_mm2: 30.875; SizeY_mm: 4.75; Value2: 0.52V; SizeZ_mm: 1.2
D12 = CMP-0029024-2: Diode, Ultrafast, 200 V, 1 A, SMA; Manufacturer: Diodes Inc.; Vf_V: 920mV; Value: 200V; Value1: 1A; Value2: 0.92V; TJmax_C: 150°C; RJC_CperW: 25; SizeAreaWB_mm2: 37.3428; SizeArea_mm2: 16.3228; SizeX_mm: 5.59; SizeY_mm: 2.92; SizeZ_mm: 2.87; AEC Category: Q101; Green_Lifecycle: Active; Green_REACh: Passed
D13 = CMP-0005583-3: Diode, TVS, Uni, 58 V, 93.6 Vc, SMB; Manufacturer: Diodes Inc.; Vbr_Max: 74.6V; AEC Category: Q101; Ppk: 600W; Vbr_Min: 64.4V; SizeX_mm: 5.6; SizeZ_mm: 2.6; SizeY_mm: 3.81; Ipp: 6.4A; Vc: 93.6V; SizeAreaWB_mm2: 44.156; SizeArea_mm2: 21.336
D14 D15 = CMP-0029032-2: Diode, Switching, 100 V, 0.2 A, SOD-123; Manufacturer: ON Semiconductor; Vf_V: 1V; Value: 100V; Value1: 0.2A; Io_A: 200mA; TJmax_C: 150°C; SizeAreaWB_mm2: 13.095; SizeArea_mm2: 6.545; SizeX_mm: 3.85; SizeY_mm: 1.7; SizeZ_mm: 1.35; AEC Category: Q101; Green_Lifecycle: Active; Green_REACh: Passed
J10 J12 = CMP-0055047-1: as J3 on sheet PMP22477_RevC_SH1
J11 = CMP-0074913-1: Terminal Block, 3.5mm Pitch, 2x1, TH; PartNumber: ED555/2DS; Manufacturer: On-Shore Technology; Cert_VDE: Y; CNHeader: False; Current_A: 6A; Green_Lifecycle: Active; Shrouded: N; Gender: Female; Green_REACh: Passed; Voltage_V: 150V; Row_Count: 1; Pitch_mm: 3.5; ContactFinish: Brass; CT: True
J13 = CMP-0074913-1: Terminal Block, 3.5mm Pitch, 2x1, TH; PartNumber: ED555/2DS; Manufacturer: On-Shore Technology; Pitch_mm: 3.5; Gender: Female; Shrouded: N; Row_Count: 1; ContactFinish: Brass; Current_A: 6A; Voltage_V: 150V; Cert_CULUS: Y; CNHeader: False; CT: True; Green_Lifecycle: Active; Green_REACh: Passed
J14 = CMP-0075405-3: Header, 100mil, 2x1, Gold, TH; Manufacturer: Samtec; Current_A: 6.3A; Green_Lifecycle: Active; Pitch_mm: 2.54; Cert_CSA: Y; Cert_VDE: N; Green_REACh: Passed; Row_Count: 1; Gender: Male; Voltage_V: 550V
L4 L6 = CMP-0003114-1: Ferrite Bead, 80 ohm @ 100 MHz, 4 A, 1206; Manufacturer: Wurth Elektronik; Ztyp@1GHz_Ohm: 134.806; ZTyp@100MHz_Ohm: 80; SizeAreaWB_mm2: 10.92; DCR_ohm: 0.025; Value1: 0.025 ohm; Value: 80 ohm; Imax_A: 4A; SizeZ_mm: 1.35; SizeX_mm: 3.2; SizeY_mm: 1.6; SizeArea_mm2: 5.12
L5 = CMP-0013075-2: Coupled inductor, 5 uH,  A, 0.0055 ohm, SMD; Manufacturer: Wurth Elektronik; Ind_H: 5µH; DCR_ohm: 5.5m
L7 = CMP-0060473-1: Inductor, Shielded Drum Core, Ferrite, 3.3 uH, 1.9 A, 0.08 ohm, SMD; Manufacturer: Coilcraft; Isat: 2A @ 30% inductance drop; Irms: 1.9A @ 40C rise; Green_Lifecycle: Not Set; SizeAreaWB_mm2: 24.01; DCR_ohm: 0.08; Green_REACh: Incomplete; Value: 3.3uH; Imax_A: 1.9A; SizeZ_mm: 1.7; SizeX_mm: 3.9; SizeArea_mm2: 15.21; Ind_H: 3.3µH; AEC Category: Q200
Q5 = CMP-0000769-1: MOSFET, N-CH, 60 V, 0.17 A, SOT-23; Alternate Manufacturer: None; Manufacturer: Diodes Inc.; SizeZ_mm: 1.1; ChType: N; Value2: 223 nC; Value1: 7; VdsMax_V: 60V; SizeX_mm: 2.5; SizeY_mm: 3; Vgs_V: 20V; Value: 60V; Rdson45_ohm: 7.5; AEC Category: Q101; IdsMax_A: 170mA; SizeAreaWB_mm2: 14; U/M: EA; QgTyp_nC: 223
Q6 = CMP-0001058-1: MOSFET, N-CH, 150 V, 4.6 A, PQFN08A; Alternate Manufacturer: None; Manufacturer: Fairchild Semiconductor; SizeZ_mm: 1.1; ChType: N; Value2: 11 nC; Value1: 0; VdsMax_V: 150V; SizeX_mm: 5; SizeY_mm: 6; Vgs_V: 20V; Value: 150V; Rdson45_ohm: 0.07; SizeArea_mm2: 30; AEC Category: Q101; IdsMax_A: 4.6A; SizeAreaWB_mm2: 56; U/M: EA; QgTyp_nC: 11
R17 = CMP-0018666-3: RES, 39 k, 5%, 0.25 W, AEC-Q200 Grade 0, 1206; PartNumber: CRCW120639K0JNEA; Manufacturer: Vishay-Dale; Value: 39k; Value_Code: 39k0; Power_W: 250mW; Value2: 0.25W; VDC_V: 200V; TempCo: 200 ppm/C; SizeArea_mm2: 5.12; SizeX_mm: 3.2; SizeY_mm: 1.6; SizeZ_mm: 1.35; EIA_Code: E24; AEC Category: Q200; AEC Qualified: Y; AEC Grade: 0
R41 = CMP-0022008-4: RES, 110 k, 1%, 0.1 W, AEC-Q200 Grade 0, 0603; Manufacturer: Vishay-Dale; Power_W: 100mW; TempCo: 100 ppm/C; Value: 110k; EIA_Code: E96; SizeX_mm: 1.6; SizeY_mm: 0.8; SizeZ_mm: 1; Value2: 0.1W; SizeArea_mm2: 1.28; AEC Qualified: Y; VDC_V: 75V; AEC Category: Q200; AEC Grade: 0
R42 R43 = CMP-0015887-3: RES, 15, 5%, 1 W, AEC-Q200 Grade 0, 2512; Manufacturer: Vishay-Dale; Power_W: 1W; TempCo: 200 ppm/C; Value_Code: 15R0; Value: 15; EIA_Code: E24; SizeX_mm: 6.3; SizeY_mm: 3.2; SizeZ_mm: 0.71; SizeArea_mm2: 20.16; AEC Qualified: Y; VDC_V: 500V; AEC Grade: 0; AEC Category: Q200
R44 R56 = CMP-0021998-4: RES, 10.0 k, 1%, 0.1 W, AEC-Q200 Grade 0, 0603; Manufacturer: Vishay-Dale; Power_W: 100mW; TempCo: 100 ppm/C; Value_Code: 10k0; Value: 10.0k; EIA_Code: E96; Res_ohm: 10k; SizeX_mm: 1.6; SizeY_mm: 0.8; SizeZ_mm: 1; Value2: 0.1W; SizeArea_mm2: 1.28; AEC Qualified: Y; VDC_V: 75V; AEC Category: Q200; AEC Grade: 0
R45 = CMP-0021831-3: RES, 3.90, 1%, 0.125 W, AEC-Q200 Grade 0, 0805; Manufacturer: Panasonic; Power_W: 125mW; TempCo: 200 ppm/C; Value_Code: 3R90; Value: 3.90; Res_ohm: 3.9; SizeX_mm: 2; SizeY_mm: 1.25; SizeZ_mm: 1.45; Value2: 0.125W; SizeArea_mm2: 2.5; AEC Qualified: Y; AEC Category: Q200; AEC Grade: 0; SizeAreaWB_mm2: 6.75
R46 = CMP-0018668-3: RES, 3.0 k, 5%, 0.25 W, AEC-Q200 Grade 0, 1206; Manufacturer: Vishay-Dale; Power_W: 250mW; TempCo: 200 ppm/C; Value_Code: 3k00; Value: 3.0k; EIA_Code: E24; Res_ohm: 3k; SizeX_mm: 3.2; SizeY_mm: 1.6; SizeZ_mm: 1.35; Value2: 0.25W; SizeArea_mm2: 5.12; AEC Qualified: Y; VDC_V: 200V; AEC Category: Q200; AEC Grade: 0
R47 = CMP-0022369-4: RES, 39.2 k, 1%, 0.1 W, AEC-Q200 Grade 0, 0603; Manufacturer: Vishay-Dale; Power_W: 100mW; TempCo: 100 ppm/C; Value_Code: 39k2; Value: 39.2k; EIA_Code: E96; SizeX_mm: 1.6; SizeY_mm: 0.8; SizeZ_mm: 1; Value2: 0.1W; SizeArea_mm2: 1.28; AEC Qualified: Y; VDC_V: 75V; AEC Category: Q200; AEC Grade: 0
R48 R49 R52 R55 R59 R60 R65 R73 = CMP-0025874-4: RES, 0, 5%, 0.1 W, AEC-Q200 Grade 0, 0603; Manufacturer: Panasonic; Power_W: 100mW; TempCo: 600 ppm/C; Value_Code: 0000; Value: 0; EIA_Code: E24; SizeX_mm: 1.6; SizeY_mm: 0.8; SizeZ_mm: 1; Value2: 0.1W; SizeArea_mm2: 1.28; AEC Qualified: Y; VDC_V: 50V; AEC Category: Q200; SizeAreaWB_mm2: 4.68
R50 = CMP-0022944-5: RES, 24.9 k, 1%, 0.1 W, 0603; Manufacturer: Yageo; Power_W: 100mW; TempCo: 100 ppm/C; Value_Code: 24k9; Value: 24.9k; EIA_Code: E96; SizeX_mm: 1.6; SizeY_mm: 0.8; SizeZ_mm: 1; Value2: 0.1W; SizeArea_mm2: 1.28; AEC Qualified: N; VDC_V: 75V; AEC Category: Q200; SizeAreaWB_mm2: 4.68
R51 = CMP-0022931-4: RES, 237 k, 1%, 0.1 W, 0603; Manufacturer: Yageo; Power_W: 100mW; TempCo: 100 ppm/C; Value: 237k; EIA_Code: E96; SizeX_mm: 1.6; SizeY_mm: 0.8; SizeZ_mm: 1; Value2: 0.1W; SizeArea_mm2: 1.28; AEC Qualified: N; VDC_V: 75V; AEC Category: Q200; SizeAreaWB_mm2: 4.68
R53 = CMP-0022532-4: RES, 60.4 k, 1%, 0.1 W, AEC-Q200 Grade 0, 0603; Manufacturer: Vishay-Dale; Power_W: 100mW; TempCo: 100 ppm/C; Value_Code: 60k4; Value: 60.4k; EIA_Code: E96; SizeX_mm: 1.6; SizeY_mm: 0.8; SizeZ_mm: 1; Value2: 0.1W; SizeArea_mm2: 1.28; AEC Qualified: Y; VDC_V: 75V; AEC Category: Q200; AEC Grade: 0
R54 = CMP-0023050-5: RES, 35.7 k, 1%, 0.1 W, 0603; Manufacturer: Yageo; Power_W: 100mW; TempCo: 100 ppm/C; Value_Code: 35k7; Value: 35.7k; EIA_Code: E96; SizeX_mm: 1.6; SizeY_mm: 0.8; SizeZ_mm: 1; Value2: 0.1W; SizeArea_mm2: 1.28; AEC Qualified: N; VDC_V: 75V; AEC Category: Q200; SizeAreaWB_mm2: 4.68
R57 R62 = CMP-0022204-4: RES, 20.0 k, 1%, 0.1 W, AEC-Q200 Grade 0, 0603; Manufacturer: Vishay-Dale; Power_W: 100mW; TempCo: 100 ppm/C; Value_Code: 20k0; Value: 20.0k; EIA_Code: E96; Res_ohm: 20k; SizeX_mm: 1.6; SizeY_mm: 0.8; SizeZ_mm: 1; Value2: 0.1W; SizeArea_mm2: 1.28; AEC Qualified: Y; VDC_V: 75V; AEC Category: Q200; AEC Grade: 0
R58 = CMP-0022458-4: RES, 4.99 k, 1%, 0.1 W, AEC-Q200 Grade 0, 0603; Manufacturer: Vishay-Dale; Power_W: 100mW; TempCo: 100 ppm/C; Value_Code: 4k99; Value: 4.99k; EIA_Code: E96; SizeX_mm: 1.6; SizeY_mm: 0.8; SizeZ_mm: 1; Value2: 0.1W; SizeArea_mm2: 1.28; AEC Qualified: Y; VDC_V: 75V; AEC Category: Q200; AEC Grade: 0
R61 = CMP-0025821-4: RES, 4.7, 5%, 0.1 W, AEC-Q200 Grade 0, 0603; Manufacturer: Vishay-Dale; Power_W: 100mW; TempCo: 200 ppm/C; Value_Code: 4R70; Value: 4.7; EIA_Code: E24; SizeX_mm: 1.6; SizeY_mm: 0.8; SizeZ_mm: 1; Value2: 0.1W; SizeArea_mm2: 1.28; AEC Qualified: Y; VDC_V: 75V; AEC Category: Q200; AEC Grade: 0
R63 = CMP-0016178-3: RES, 75, 5%, 0.75 W, AEC-Q200 Grade 0, 2010; Manufacturer: Vishay-Dale; Power_W: 750mW; TempCo: 200 ppm/C; Value_Code: 75R0; Value: 75; EIA_Code: E24; SizeX_mm: 5; SizeY_mm: 2.5; SizeZ_mm: 1.66; Value2: 0.75W; SizeArea_mm2: 12.5; AEC Qualified: Y; VDC_V: 400V; AEC Grade: 0; AEC Category: Q200
R64 = CMP-0022447-4: RES, 49.9 k, 1%, 0.1 W, AEC-Q200 Grade 0, 0603; Manufacturer: Vishay-Dale; Power_W: 100mW; TempCo: 100 ppm/C; Value_Code: 49k9; Value: 49.9k; EIA_Code: E96; SizeX_mm: 1.6; SizeY_mm: 0.8; SizeZ_mm: 1; Value2: 0.1W; SizeArea_mm2: 1.28; AEC Qualified: Y; VDC_V: 75V; AEC Category: Q200; AEC Grade: 0
R66 = CMP-0018594-3: RES, 15, 5%, 0.25 W, AEC-Q200 Grade 0, 1206; Manufacturer: Vishay-Dale; Power_W: 250mW; TempCo: 200 ppm/C; Value_Code: 15R0; Value: 15; EIA_Code: E24; SizeX_mm: 3.2; SizeY_mm: 1.6; SizeZ_mm: 1.35; Value2: 0.25W; SizeArea_mm2: 5.12; AEC Qualified: Y; VDC_V: 200V; AEC Category: Q200; AEC Grade: 0
R67 = CMP-0016520-2: RES, 0.05, 1%, 1 W, 2010; Manufacturer: Stackpole Electronics Inc; Power_W: 1W; TempCo: 250 ppm/C; Value_Code: R050; U/M: EA; Value: 0.05; EIA_Code: E96; SizeX_mm: 5; SizeY_mm: 2.5; SizeZ_mm: 1.66; SizeArea_mm2: 12.5; AEC Category: Q200
R68 = CMP-0021169-3: RES, 31.6, 1%, 0.125 W, AEC-Q200 Grade 0, 0805; Manufacturer: Vishay-Dale; Power_W: 125mW; TempCo: 100 ppm/C; Value_Code: 31R6; Value: 31.6; EIA_Code: E96; SizeX_mm: 2; SizeY_mm: 1.25; SizeZ_mm: 1.45; Value2: 0.125W; SizeArea_mm2: 2.5; AEC Qualified: Y; VDC_V: 150V; AEC Category: Q200; AEC Grade: 0
R69 = CMP-0020880-3: RES, 130, 1%, 0.125 W, AEC-Q200 Grade 0, 0805; Manufacturer: Vishay-Dale; Power_W: 125mW; TempCo: 100 ppm/C; Value_Code: 130R; Value: 130; EIA_Code: E96; SizeX_mm: 2; SizeY_mm: 1.25; SizeZ_mm: 1.45; Value2: 0.125W; SizeArea_mm2: 2.5; AEC Qualified: Y; VDC_V: 150V; AEC Category: Q200; AEC Grade: 0
R70 = CMP-0025851-4: RES, 750 k, 5%, 0.1 W, AEC-Q200 Grade 0, 0603; Manufacturer: Vishay-Dale; Power_W: 100mW; TempCo: 200 ppm/C; Value: 750k; EIA_Code: E24; SizeX_mm: 1.6; SizeY_mm: 0.8; SizeZ_mm: 1; Value2: 0.1W; SizeArea_mm2: 1.28; AEC Qualified: Y; VDC_V: 75V; AEC Category: Q200; AEC Grade: 0
R71 = CMP-0022951-5: RES, 25.5 k, 1%, 0.1 W, 0603; Manufacturer: Yageo; Power_W: 100mW; TempCo: 100 ppm/C; Value_Code: 25k5; Value: 25.5k; EIA_Code: E96; SizeX_mm: 1.6; SizeY_mm: 0.8; SizeZ_mm: 1; Value2: 0.1W; SizeArea_mm2: 1.28; AEC Qualified: N; VDC_V: 75V; AEC Category: Q200; SizeAreaWB_mm2: 4.68
R72 = CMP-0022109-5: RES, 1.00 k, 1%, 0.1 W, AEC-Q200 Grade 0, 0603; Manufacturer: Vishay-Dale; Power_W: 100mW; TempCo: 100 ppm/C; Value_Code: 1k00; Value: 1.00k; EIA_Code: E96; Res_ohm: 1k; SizeX_mm: 1.6; SizeY_mm: 0.8; SizeZ_mm: 1; Value2: 0.1W; SizeArea_mm2: 1.28; AEC Qualified: Y; VDC_V: 75V; AEC Category: Q200; AEC Grade: 0
R74 = CMP-0022445-4: RES, 499 k, 1%, 0.1 W, AEC-Q200 Grade 0, 0603; Manufacturer: Vishay-Dale; Power_W: 100mW; TempCo: 100 ppm/C; Value: 499k; EIA_Code: E96; SizeX_mm: 1.6; SizeY_mm: 0.8; SizeZ_mm: 1; Value2: 0.1W; SizeArea_mm2: 1.28; AEC Qualified: Y; VDC_V: 75V; AEC Category: Q200; AEC Grade: 0
T2 = CMP-0088826-2: Transformer; Manufacturer: LinkCom; SizeZ_mm: 14.5mm; Frequency_Fixed: 250kHz; AEC Qualified: No
U10 = CMP-0860918-1: TPS23730RMT, RMT0045A (VQFN-45); Alternate Manufacturer: Texas Instruments; SizeArea_mm2: 35; CompType: IC; SizeY_mm: 7; SizeAreaWB_mm2: 63; AEC Category: Q200; SizeZ_mm: 1; AEC Qualified: N; SizeX_mm: 5
U11 = CMP-0006165-3: Optocoupler, 5 kV, 300-600% CTR, SMT; Manufacturer: Fairchild Semiconductor; CTR (Min): 300%; CTR (Max): 600%; Voltage_Isolation_Vrms: 5kV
